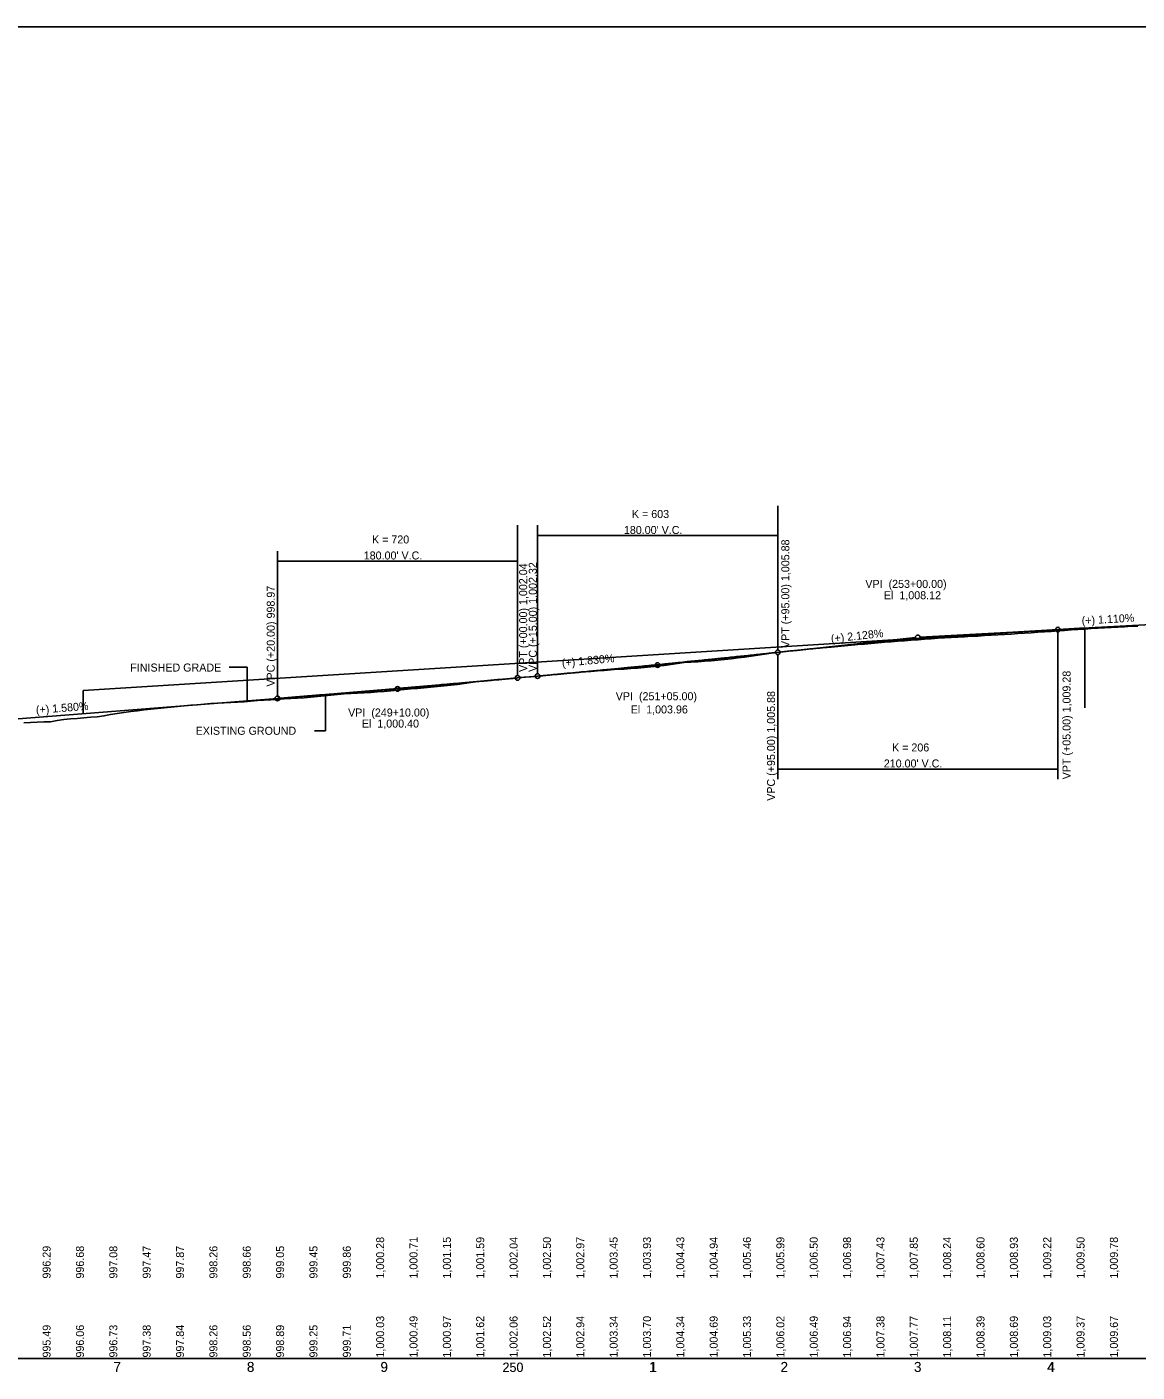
# Model space of a CAD drawing. Extents: x 1608361 to 16979326, y 1092015 to 12565288.
# Drawn here: x 16973618 to 16974450, y 12564278 to 12565286 of the extents above; entities that cross this region are included whole.
import ezdxf

# ---------------------------------------------------------------- set-up
doc = ezdxf.new("R2010")
doc.units = 0
for name, color, linetype in [('CLS_Median', 7, 'Continuous'), ('Default', 7, 'Continuous'), ('points EP', 7, 'Continuous'), ('RD_DDB_EX_Tx', 7, 'Continuous'), ('RD_EX_Fence_ChLk', 7, 'Continuous'), ('RD_EX_H2O', 7, 'Continuous'), ('RD_EX_RW_Approx', 7, 'Continuous'), ('RD_EX_SU_Water', 7, 'Continuous'), ('RD_EX_UT', 7, 'Continuous'), ('RD_HC_TX_Rel_Sta50', 7, 'Continuous'), ('RD_PD_BCA', 7, 'Continuous'), ('RD_PD_Final_TX', 7, 'Continuous'), ('TEXT2', 7, 'Continuous')]:
    doc.layers.add(name, color=color, linetype=linetype)

msp = doc.modelspace()

# ---------------------------------------------------------------- linework, layer by layer
at = {"layer": 'CLS_Median'}
for p, q in [((16973769.5, 12564806), (16973782.9, 12564806)), ((16973782.9, 12564806), (16973782.9, 12564780.9))]:
    msp.add_line(p, q, dxfattribs=at)
at = {"layer": 'Default'}
msp.add_lwpolyline([(16972985.6, 12564287.8), (16974485.6, 12564287.8), (16974485.6, 12565286), (16972985.6, 12565286)], close=True, dxfattribs=at)
at = {"layer": 'RD_DDB_EX_Tx'}
for p, q in [((16973841.7, 12564758.4), (16973841.7, 12564784.1)), ((16973833.5, 12564758.4), (16973841.7, 12564758.4))]:
    msp.add_line(p, q, dxfattribs=at)
at = {"layer": 'RD_EX_Fence_ChLk'}
for p, q in [((16974180.6, 12564927), (16974180.6, 12564818.9)), ((16973985.6, 12564912.4), (16973985.6, 12564799.8)), ((16974000.6, 12564912.4), (16974000.6, 12564801.1)), ((16974000.6, 12564904.7), (16974180.6, 12564904.7)), ((16973805.6, 12564893), (16973805.6, 12564784.4)), ((16973805.6, 12564885.5), (16973985.6, 12564885.5)), ((16974390.6, 12564722.2), (16974390.6, 12564832.4)), ((16974180.6, 12564722.2), (16974180.6, 12564815.4)), ((16974180.6, 12564729.7), (16974390.6, 12564729.7))]:
    msp.add_line(p, q, dxfattribs=at)
for centre in [(16974390.6, 12564834.2), (16974180.6, 12564817.2), (16974180.6, 12564817.2), (16973985.6, 12564798), (16974000.6, 12564799.4), (16973805.6, 12564782.7)]:
    msp.add_circle(centre, 1.75, dxfattribs=at)
at = {"layer": 'RD_EX_H2O'}
for points in [[(16973985.6, 12564798.1), (16973990.6, 12564798.5), (16973995.6, 12564798.9), (16974000.6, 12564799.4), (16974005.6, 12564799.8), (16974010.6, 12564800.4), (16974015.6, 12564800.9), (16974020.6, 12564801.3), (16974025.6, 12564801.7), (16974030.6, 12564802.1), (16974035.6, 12564802.5), (16974040.6, 12564802.9), (16974045.6, 12564803.3), (16974050.6, 12564803.7), (16974055.6, 12564804.1), (16974060.6, 12564804.5), (16974065.6, 12564804.7), (16974070.6, 12564805), (16974075.6, 12564805.4), (16974080.6, 12564805.8), (16974085.6, 12564806.3), (16974090.6, 12564806.8), (16974095.6, 12564807.3), (16974100.6, 12564808.1), (16974105.6, 12564808.9), (16974110.6, 12564809.5), (16974115.6, 12564809.8), (16974120.6, 12564810.2), (16974125.6, 12564810.5), (16974130.6, 12564810.9), (16974135.6, 12564811.3), (16974140.6, 12564811.8), (16974145.6, 12564812.4), (16974150.6, 12564813), (16974155.6, 12564813.7), (16974160.6, 12564814.4), (16974165.6, 12564815.1), (16974170.6, 12564815.8), (16974175.6, 12564816.5), (16974180.6, 12564817.2), (16974185.6, 12564817.9), (16974190.6, 12564818.4), (16974195.6, 12564818.9), (16974200.6, 12564819.3), (16974205.6, 12564819.8), (16974210.6, 12564820.2), (16974215.6, 12564820.7), (16974220.6, 12564821.1), (16974225.6, 12564821.6), (16974230.6, 12564822), (16974235.6, 12564822.5), (16974240.6, 12564823), (16974245.6, 12564823.4), (16974250.6, 12564823.9), (16974255.6, 12564824.3), (16974260.6, 12564824.7), (16974265.6, 12564825.1), (16974270.6, 12564825.5), (16974275.6, 12564825.9), (16974280.6, 12564826.2), (16974285.6, 12564826.6), (16974290.6, 12564827), (16974295.6, 12564827.4), (16974300.6, 12564827.7), (16974305.6, 12564828), (16974310.6, 12564828.3), (16974315.6, 12564828.6), (16974320.6, 12564828.9), (16974325.6, 12564829.2), (16974330.6, 12564829.4), (16974335.6, 12564829.7), (16974340.6, 12564830), (16974345.6, 12564830.3), (16974350.6, 12564830.6), (16974355.6, 12564830.9), (16974360.6, 12564831.3), (16974365.6, 12564831.6), (16974370.6, 12564831.9), (16974375.6, 12564832.3), (16974380.6, 12564832.6), (16974385.6, 12564832.9), (16974390.6, 12564833.3), (16974395.6, 12564833.6), (16974400.6, 12564834), (16974405.6, 12564834.3), (16974410.6, 12564834.6), (16974415.6, 12564835.1), (16974420.6, 12564835.3), (16974425.6, 12564835.6), (16974430.6, 12564835.9), (16974435.6, 12564836.1), (16974440.6, 12564836.4), (16974445.6, 12564836.7), (16974450.6, 12564836.9)], [(16973615.6, 12564764.4), (16973620.6, 12564764.7), (16973625.6, 12564764.9), (16973630.6, 12564765), (16973635.6, 12564765.2), (16973640.6, 12564766.1), (16973645.6, 12564766.9), (16973650.6, 12564767.3), (16973655.6, 12564767.7), (16973660.6, 12564768.1), (16973665.6, 12564768.5), (16973670.6, 12564768.8), (16973675.6, 12564769.6), (16973680.6, 12564770.5), (16973685.6, 12564771.4), (16973690.6, 12564772.2), (16973695.6, 12564772.8), (16973700.6, 12564773.4), (16973705.6, 12564774), (16973710.6, 12564774.7), (16973715.6, 12564775.2), (16973720.6, 12564775.7), (16973725.6, 12564776.1), (16973730.6, 12564776.6), (16973735.6, 12564777), (16973740.6, 12564777.5), (16973745.6, 12564777.9), (16973750.6, 12564778.3), (16973755.6, 12564778.8), (16973760.6, 12564779.1), (16973765.6, 12564779.3), (16973770.6, 12564779.5), (16973775.6, 12564779.8), (16973780.6, 12564780.1), (16973785.6, 12564780.6), (16973790.6, 12564781), (16973795.6, 12564781.3), (16973800.6, 12564781.6), (16973805.6, 12564781.9), (16973810.6, 12564782.3), (16973815.6, 12564782.6), (16973820.6, 12564782.9), (16973825.6, 12564783.2), (16973830.6, 12564783.5), (16973835.6, 12564784), (16973840.6, 12564784.5), (16973845.6, 12564785), (16973850.6, 12564785.5), (16973855.6, 12564786), (16973860.6, 12564786.3), (16973865.6, 12564786.6), (16973870.6, 12564786.9), (16973875.6, 12564787.2), (16973880.6, 12564787.5), (16973885.6, 12564787.9), (16973890.6, 12564788.3), (16973895.6, 12564788.8), (16973900.6, 12564789.3), (16973905.6, 12564789.8), (16973910.6, 12564790.2), (16973915.6, 12564790.7), (16973920.6, 12564791.2), (16973925.6, 12564791.7), (16973930.6, 12564792.2), (16973935.6, 12564792.6), (16973940.6, 12564793.2), (16973945.6, 12564793.9), (16973950.6, 12564794.6), (16973955.6, 12564795.3), (16973960.6, 12564795.9), (16973965.6, 12564796.3), (16973970.6, 12564796.8), (16973975.6, 12564797.2), (16973980.6, 12564797.6), (16973985.6, 12564798.1)]]:
    msp.add_lwpolyline(points, dxfattribs=at)
at = {"layer": 'RD_EX_RW_Approx'}
for p, q in [((16974196.1, 12564818.8), (16974283.8, 12564828.2)), ((16974375.4, 12564833.4), (16974287.3, 12564828.5)), ((16974180, 12564817.1), (16974092.3, 12564807.8)), ((16974000.9, 12564799.4), (16974088.8, 12564807.5)), ((16973985.2, 12564798), (16973897.3, 12564789.9)), ((16973805.8, 12564782.7), (16973893.8, 12564789.6))]:
    msp.add_line(p, q, dxfattribs=at)
for centre in [(16974285.6, 12564828.4), (16974090.6, 12564807.6), (16973895.6, 12564789.8)]:
    msp.add_circle(centre, 1.75, dxfattribs=at)
at = {"layer": 'RD_EX_UT'}
msp.add_line((16972985.6, 12564287.8), (16978789.9, 12564287.8), dxfattribs=at)
at = {"layer": 'RD_HC_TX_Rel_Sta50'}
for p, q in [((16974390.6, 12564834.2), (16974460.6, 12564838.1)), ((16973985.6, 12564798), (16974000.6, 12564799.4)), ((16973510.6, 12564759.4), (16973805.6, 12564782.7))]:
    msp.add_line(p, q, dxfattribs=at)
for points in [[(16974180.6, 12564817.2), (16974184.8, 12564817.6), (16974189, 12564818.1), (16974193.2, 12564818.5), (16974197.4, 12564818.9), (16974201.6, 12564819.4), (16974205.8, 12564819.8), (16974210, 12564820.2), (16974214.2, 12564820.6), (16974218.4, 12564821), (16974222.6, 12564821.4), (16974226.8, 12564821.8), (16974231, 12564822.2), (16974235.2, 12564822.6), (16974239.4, 12564823), (16974243.6, 12564823.4), (16974247.8, 12564823.8), (16974252, 12564824.2), (16974256.2, 12564824.5), (16974260.4, 12564824.9), (16974264.6, 12564825.3), (16974268.8, 12564825.6), (16974273, 12564826), (16974277.2, 12564826.3), (16974281.4, 12564826.7), (16974285.6, 12564827), (16974289.8, 12564827.4), (16974294, 12564827.7), (16974298.2, 12564828), (16974302.4, 12564828.4), (16974306.6, 12564828.7), (16974310.8, 12564829), (16974315, 12564829.3), (16974319.2, 12564829.6), (16974323.4, 12564829.9), (16974327.6, 12564830.2), (16974331.8, 12564830.5), (16974336, 12564830.8), (16974340.2, 12564831.1), (16974344.4, 12564831.4), (16974348.6, 12564831.6), (16974352.8, 12564831.9), (16974357, 12564832.2), (16974361.2, 12564832.5), (16974365.4, 12564832.7), (16974369.6, 12564833), (16974373.8, 12564833.2), (16974378, 12564833.5), (16974382.2, 12564833.7), (16974386.4, 12564834), (16974390.6, 12564834.2)], [(16974000.6, 12564799.4), (16974004.2, 12564799.7), (16974007.8, 12564800), (16974011.4, 12564800.4), (16974015, 12564800.7), (16974018.6, 12564801), (16974022.2, 12564801.4), (16974025.8, 12564801.7), (16974029.4, 12564802), (16974033, 12564802.4), (16974036.6, 12564802.7), (16974040.2, 12564803.1), (16974043.8, 12564803.4), (16974047.4, 12564803.8), (16974051, 12564804.1), (16974054.6, 12564804.4), (16974058.2, 12564804.8), (16974061.8, 12564805.1), (16974065.4, 12564805.5), (16974069, 12564805.8), (16974072.6, 12564806.2), (16974076.2, 12564806.5), (16974079.8, 12564806.9), (16974083.4, 12564807.2), (16974087, 12564807.6), (16974090.6, 12564807.9), (16974094.2, 12564808.3), (16974097.8, 12564808.7), (16974101.4, 12564809), (16974105, 12564809.4), (16974108.6, 12564809.7), (16974112.2, 12564810.1), (16974115.8, 12564810.5), (16974119.4, 12564810.8), (16974123, 12564811.2), (16974126.6, 12564811.6), (16974130.2, 12564811.9), (16974133.8, 12564812.3), (16974137.4, 12564812.7), (16974141, 12564813), (16974144.6, 12564813.4), (16974148.2, 12564813.8), (16974151.8, 12564814.2), (16974155.4, 12564814.5), (16974159, 12564814.9), (16974162.6, 12564815.3), (16974166.2, 12564815.7), (16974169.8, 12564816), (16974173.4, 12564816.4), (16974177, 12564816.8), (16974180.6, 12564817.2)], [(16973805.6, 12564782.7), (16973809.2, 12564782.9), (16973812.8, 12564783.2), (16973816.4, 12564783.5), (16973820, 12564783.8), (16973823.6, 12564784.1), (16973827.2, 12564784.4), (16973830.8, 12564784.7), (16973834.4, 12564785), (16973838, 12564785.3), (16973841.6, 12564785.5), (16973845.2, 12564785.8), (16973848.8, 12564786.1), (16973852.4, 12564786.4), (16973856, 12564786.7), (16973859.6, 12564787), (16973863.2, 12564787.3), (16973866.8, 12564787.6), (16973870.4, 12564787.9), (16973874, 12564788.2), (16973877.6, 12564788.5), (16973881.2, 12564788.8), (16973884.8, 12564789.1), (16973888.4, 12564789.4), (16973892, 12564789.7), (16973895.6, 12564790.1), (16973899.2, 12564790.4), (16973902.8, 12564790.7), (16973906.4, 12564791), (16973910, 12564791.3), (16973913.6, 12564791.6), (16973917.2, 12564791.9), (16973920.8, 12564792.2), (16973924.4, 12564792.5), (16973928, 12564792.9), (16973931.6, 12564793.2), (16973935.2, 12564793.5), (16973938.8, 12564793.8), (16973942.4, 12564794.1), (16973946, 12564794.4), (16973949.6, 12564794.8), (16973953.2, 12564795.1), (16973956.8, 12564795.4), (16973960.4, 12564795.7), (16973964, 12564796), (16973967.6, 12564796.4), (16973971.2, 12564796.7), (16973974.8, 12564797), (16973978.4, 12564797.3), (16973982, 12564797.7), (16973985.6, 12564798)]]:
    msp.add_spline(points, degree=3, dxfattribs=at)
at = {"layer": 'RD_PD_BCA'}
for p, q in [((16973660, 12564788.7), (16974410.8, 12564835.5)), ((16974410.8, 12564835.5), (16974410.8, 12564775.7)), ((16973660, 12564771.2), (16973660, 12564788.7))]:
    msp.add_line(p, q, dxfattribs=at)

# ---------------------------------------------------------------- texts
at = {"layer": 'CLS_Median'}
msp.add_text('FINISHED GRADE', height=6, dxfattribs=at).set_placement((16973695.3, 12564802.8))
at = {"layer": 'points EP'}
for s, rotation, p in [('(+) 1.110%', 3.1767, (16974408.6, 12564838)), ('(+) 2.128%', 6.0747, (16974220.8, 12564824.5)), ('(+) 1.830%', 5.228, (16974019.1, 12564806.3)), ('(+) 1.580%', 4.517, (16973624.8, 12564771))]:
    msp.add_text(s, height=6, rotation=rotation, dxfattribs=at).set_placement(p)
at = {"layer": 'RD_DDB_EX_Tx'}
msp.add_text('EXISTING GROUND', height=6, dxfattribs=at).set_placement((16973744.3, 12564755.4))
at = {"layer": 'RD_EX_Fence_ChLk'}
for s, p in [('K = 603', (16974071.3, 12564917.9)), ("180.00' V.C.", (16974065.3, 12564905.9)), ('K = 720', (16973876.5, 12564898.8)), ("180.00' V.C.", (16973870.3, 12564886.8)), ('K = 206', (16974266.3, 12564742.9)), ("210.00' V.C.", (16974260.1, 12564730.9))]:
    msp.add_text(s, height=6, dxfattribs=at).set_placement(p)
for s, p in [('VPT (+95.00) 1,005.88', (16974189.3, 12564820.4)), ('VPT (+00.00) 1,002.04', (16973992.8, 12564802.5)), ('VPC (+15.00) 1,002.32', (16974000, 12564802.5)), ('VPC (+20.00) 998.97', (16973803.6, 12564791.5)), ('VPT (+05.00) 1,009.28', (16974400.1, 12564722)), ('VPC (+95.00) 1,005.88', (16974178.6, 12564705.9))]:
    msp.add_text(s, height=6, rotation=90, dxfattribs=at).set_placement(p)
at = {"layer": 'RD_EX_RW_Approx'}
for s, p in [('VPI  (253+00.00)', (16974246.3, 12564865.5)), ('El  1,008.12', (16974260.2, 12564857)), ('VPI  (251+05.00)', (16974059.2, 12564781.3)), ('El  1,003.96', (16974070.4, 12564771.4)), ('VPI  (249+10.00)', (16973858.6, 12564769.1)), ('El  1,000.40', (16973868.9, 12564760.8))]:
    msp.add_text(s, height=6, dxfattribs=at).set_placement(p)
at = {"layer": 'RD_EX_SU_Water'}
for s, p in [('1,000.28', (16973885.6, 12564347.8)), ('1,000.71', (16973910.6, 12564347.8)), ('1,001.15', (16973935.6, 12564347.8)), ('1,001.59', (16973960.6, 12564347.8)), ('1,002.04', (16973985.6, 12564347.8)), ('1,002.50', (16974010.6, 12564347.8)), ('1,002.97', (16974035.6, 12564347.8)), ('1,003.45', (16974060.6, 12564347.8)), ('1,003.93', (16974085.6, 12564347.8)), ('1,004.43', (16974110.6, 12564347.8)), ('1,004.94', (16974135.6, 12564347.8)), ('1,005.46', (16974160.6, 12564347.8)), ('1,005.99', (16974185.6, 12564347.8)), ('1,006.50', (16974210.6, 12564347.8)), ('1,006.98', (16974235.6, 12564347.8)), ('1,007.43', (16974260.6, 12564347.8)), ('1,007.85', (16974285.6, 12564347.8)), ('1,008.24', (16974310.6, 12564347.8)), ('1,008.60', (16974335.6, 12564347.8)), ('1,008.93', (16974360.6, 12564347.8)), ('1,009.22', (16974385.6, 12564347.8)), ('1,009.50', (16974410.6, 12564347.8)), ('1,009.78', (16974435.6, 12564347.8)), ('996.29', (16973635.6, 12564347.8)), ('996.68', (16973660.6, 12564347.8)), ('997.08', (16973685.6, 12564347.8)), ('997.47', (16973710.6, 12564347.8)), ('997.87', (16973735.6, 12564347.8)), ('998.26', (16973760.6, 12564347.8)), ('998.66', (16973785.6, 12564347.8)), ('999.05', (16973810.6, 12564347.8)), ('999.45', (16973835.6, 12564347.8)), ('999.86', (16973860.6, 12564347.8))]:
    msp.add_text(s, height=6, rotation=90, dxfattribs=at).set_placement(p)
at = {"layer": 'RD_PD_Final_TX'}
for s, height, p in [('7', 7.5, (16973682.7, 12564277.8)), ('7', 7.5, (16973682.8, 12564277.8)), ('8', 7.5, (16973782.7, 12564277.8)), ('8', 7.5, (16973782.8, 12564277.8)), ('9', 7.5, (16973882.8, 12564277.8)), ('9', 7.5, (16973882.9, 12564277.8)), ('250', 7, (16973974.3, 12564277.8)), ('250', 7, (16973974.4, 12564277.8)), ('1', 7.5, (16974084.2, 12564277.8)), ('1', 7.5, (16974084.6, 12564277.8)), ('2', 7.5, (16974182.7, 12564277.8)), ('2', 7.5, (16974182.8, 12564277.8)), ('3', 7.5, (16974282.7, 12564277.8)), ('3', 7.5, (16974282.8, 12564277.8)), ('4', 7.5, (16974382.5, 12564277.8)), ('4', 7.5, (16974382.8, 12564277.8))]:
    msp.add_text(s, height=height, dxfattribs=at).set_placement(p)
at = {"layer": 'TEXT2'}
for s, p in [('995.49', (16973635.6, 12564288.6)), ('996.06', (16973660.6, 12564288.6)), ('996.73', (16973685.6, 12564288.6)), ('997.38', (16973710.6, 12564288.6)), ('997.84', (16973735.6, 12564288.6)), ('998.26', (16973760.6, 12564288.6)), ('998.56', (16973785.6, 12564288.6)), ('998.89', (16973810.6, 12564288.6)), ('999.25', (16973835.6, 12564288.6)), ('999.71', (16973860.6, 12564288.6)), ('1,000.03', (16973885.6, 12564288.6)), ('1,000.49', (16973910.6, 12564288.6)), ('1,000.97', (16973935.6, 12564288.6)), ('1,001.62', (16973960.6, 12564288.6)), ('1,002.06', (16973985.6, 12564288.6)), ('1,002.52', (16974010.6, 12564288.6)), ('1,002.94', (16974035.6, 12564288.6)), ('1,003.34', (16974060.6, 12564288.6)), ('1,003.70', (16974085.6, 12564288.6)), ('1,004.34', (16974110.6, 12564288.6)), ('1,004.69', (16974135.6, 12564288.6)), ('1,005.33', (16974160.6, 12564288.6)), ('1,006.02', (16974185.6, 12564288.6)), ('1,006.49', (16974210.6, 12564288.6)), ('1,006.94', (16974235.6, 12564288.6)), ('1,007.38', (16974260.6, 12564288.6)), ('1,007.77', (16974285.6, 12564288.6)), ('1,008.11', (16974310.6, 12564288.6)), ('1,008.39', (16974335.6, 12564288.6)), ('1,008.69', (16974360.6, 12564288.6)), ('1,009.03', (16974385.6, 12564288.6)), ('1,009.37', (16974410.6, 12564288.6)), ('1,009.67', (16974435.6, 12564288.6))]:
    msp.add_text(s, height=6, rotation=90, dxfattribs=at).set_placement(p)

doc.saveas('drawing.dxf')
